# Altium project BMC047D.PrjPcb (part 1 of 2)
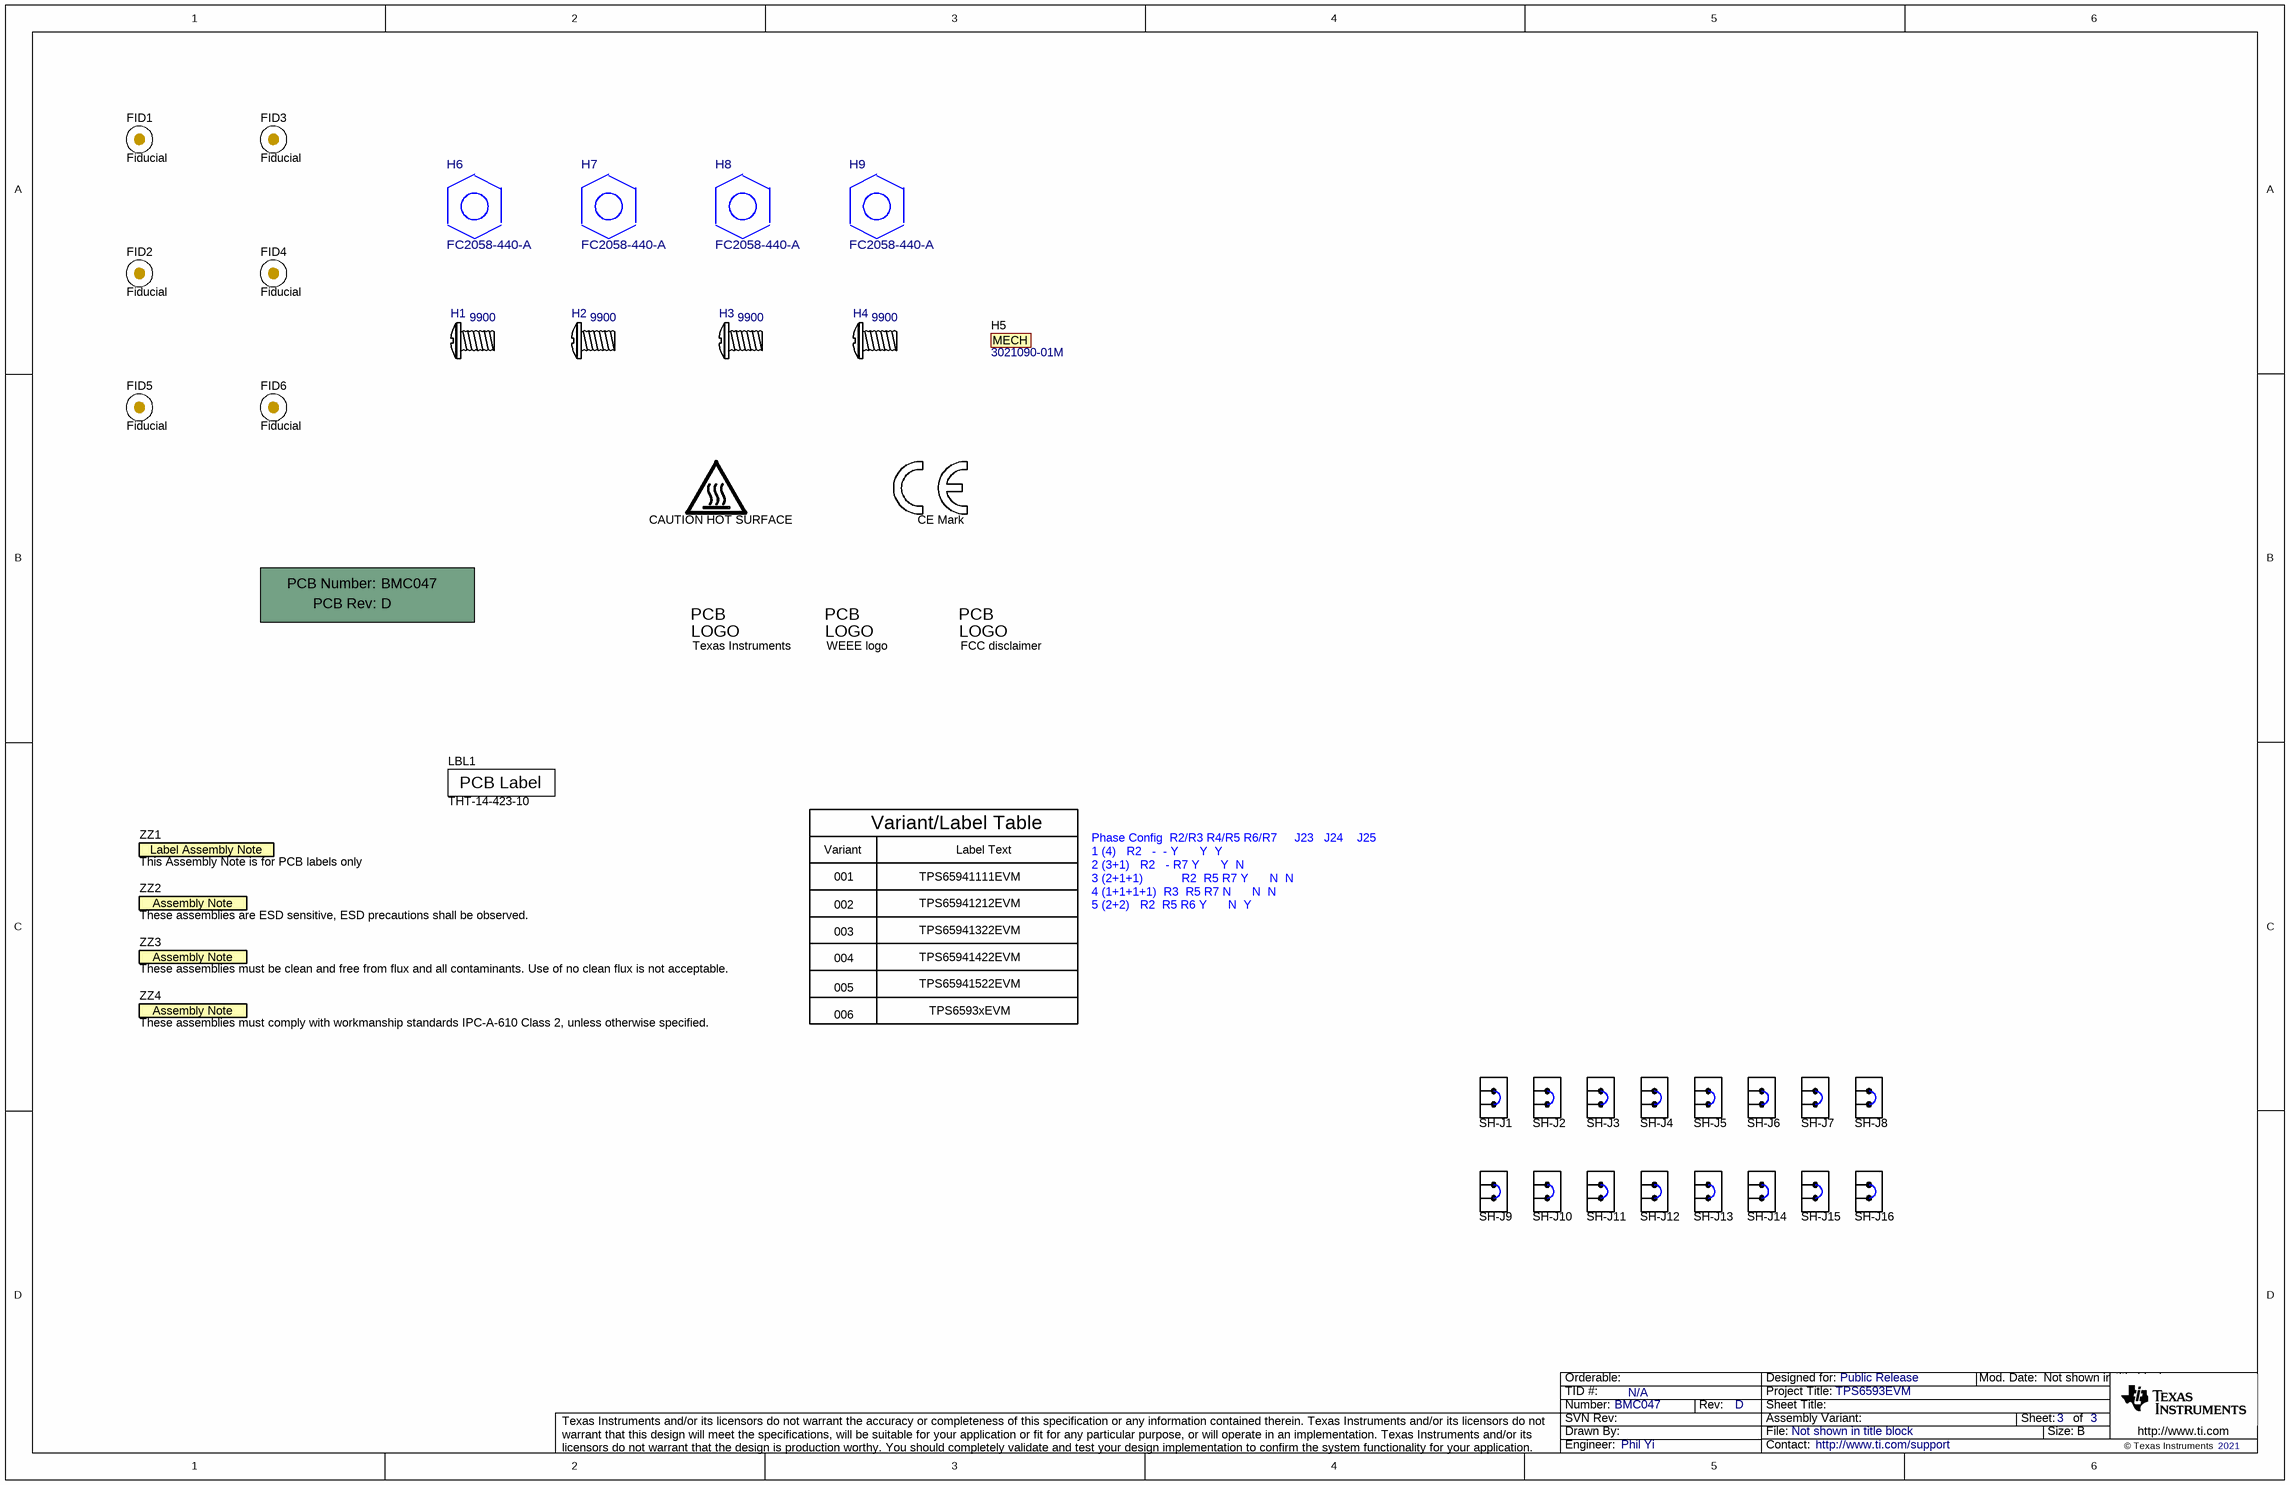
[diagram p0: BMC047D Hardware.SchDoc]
TID: N/A; TechSupport: http://www.ti.com/support; SCH_Rev: D; PRJ_Title: TPS6593EVM; PRJ_Number: BMC047; PRJ_Engineer: Phil Yi; PRJ_Customer: Public Release; PCB_Rev: D; PCB_Layout: Phil Yi; CopyrightYear: 2021
3 sheets, 331 parts. Net scope: global (net labels, ports and power ports of the same name join across sheets).
Board file: BMC047D.PcbDoc
Sheets:
  BMC047D Hardware.SchDoc
  BMC047D Main.SchDoc
  BMC047D USB.SchDoc

## Sheet BMC047D Hardware.SchDoc
size 431 x 279 mm; Date: Not shown in title block; ApprovedBy: Not shown in title block; CheckedBy: Not shown in title block; Author: Not shown in title block; CompanyName: Not shown in title block; Engineer: Not shown in title block; Organization: Not shown in title block; Address1: Not shown in title block; Address2: Not shown in title block; Address3: Not shown in title block; Address4: Not shown in title block; DocumentNumber: 3; Revision: Use project parameter SCH_Rev; SheetNumber: 3; SheetTotal: 3; PageSetup: Record=PageOptions¦CenterHorizontal=True¦CenterVertical=True¦PrintScale=1.00¦XCorrection=1.00¦YCorrection=1.00¦PrintKind=0¦BorderSize=5000000¦LeftOffset=0¦BottomOffset=0¦Orientation=2¦PaperLength=1000¦PaperWidth=1000¦Scale=100¦PaperSource=15¦PrintQuality=600¦MediaType=1¦DitherType=10¦PaperKind=Letter¦PrintScaleMode=1

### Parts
!PCB1  Printed Circuit Board  (value not drawn)  (mechanical)
FID1  Fiducial  [Fiducial10-30]  (no BOM)
FID2  Fiducial  [Fiducial10-30]  (no BOM)
FID3  Fiducial  [Fiducial10-30]  (no BOM)
FID4  Fiducial  [Fiducial10-30]  (no BOM)
FID5  Fiducial  [Fiducial10-30]  (no BOM)
FID6  Fiducial  [Fiducial10-30]  (no BOM)
H1  9900  (mechanical)
H2  9900  (mechanical)
H3  9900  (mechanical)
H4  9900  (mechanical)
H5  3021090-01M  (mechanical)
H6  FC2058-440-A  [FP-FC2058-440-A_SPACER-MFG]  (mechanical)
H7  FC2058-440-A  [FP-FC2058-440-A_SPACER-MFG]  (mechanical)
H8  FC2058-440-A  [FP-FC2058-440-A_SPACER-MFG]  (mechanical)
H9  FC2058-440-A  [FP-FC2058-440-A_SPACER-MFG]  (mechanical)
LBL1  THT-14-423-10  [Label_650x200]
LOGO1  CAUTION HOT SURFACE  [IEC_HotSurface_Small]  (no BOM)
Logo2  Texas Instruments  [TI_Stacked_Overlay_Small]  (no BOM)
Logo3  WEEE logo  [WEEE_Minimum]  (no BOM)
Logo4  CE Mark  [CE_Mark_5mm]  (no BOM)
Logo5  FCC disclaimer  [FCC_disclaimer_stacked]  (no BOM)
SH-J1  881545-2  [TE_881545-2]  (value not drawn)
SH-J2  881545-2  [TE_881545-2]  (value not drawn)
SH-J3  881545-2  [TE_881545-2]  (value not drawn)
SH-J4  881545-2  [TE_881545-2]  (value not drawn)
SH-J5  881545-2  [TE_881545-2]  (value not drawn)
SH-J6  881545-2  [TE_881545-2]  (value not drawn)
SH-J7  881545-2  [TE_881545-2]  (value not drawn)
SH-J8  881545-2  [TE_881545-2]  (value not drawn)
SH-J9  881545-2  [TE_881545-2]  (value not drawn)
SH-J10  881545-2  [TE_881545-2]  (value not drawn)
SH-J11  881545-2  [TE_881545-2]  (value not drawn)
SH-J12  881545-2  [TE_881545-2]  (value not drawn)
SH-J13  881545-2  [TE_881545-2]  (value not drawn)
SH-J14  881545-2  [TE_881545-2]  (value not drawn)
SH-J15  881545-2  [TE_881545-2]  (value not drawn)
SH-J16  881545-2  [TE_881545-2]  (value not drawn)
ZZ1  This Assembly Note is for PCB labels only  [AssemblyNoteLabel]  (no BOM)
ZZ2  These assemblies are ESD sensitive, ESD precautions shall be observed.  [AssemblyNote]  (no BOM)
ZZ3  These assemblies must be clean and free from flux and all contaminants. Use of no clean flux is not acceptable.  [AssemblyNote]  (no BOM)
ZZ4  These assemblies must comply with workmanship standards IPC-A-610 Class 2, unless otherwise specified.  [AssemblyNote]  (no BOM)

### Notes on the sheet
- Variant/Label Table
- Variant
- 001
- 002
- TPS65941111EVM
- TPS65941212EVM
- Label Text
- 003
- 004
- TPS65941322EVM
- TPS65941422EVM
- Phase Config	 R2/R3	R4/R5	R6/R7     J23   J24    J25
  1 (4)		 R2	  -	 -	Y      Y	 Y
  2 (3+1)		 R2	  -	R7	Y      Y	 N
  3 (2+1+1)	        	 R2	 R5	R7	Y      N	 N
  4 (1+1+1+1)	 R3	 R5	R7	N      N	 N
  5 (2+2)		 R2	 R5	R6	Y      N	 Y
- 005
- 006
- TPS65941522EVM
- TPS6593xEVM

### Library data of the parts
!PCB1 = CMP-0003618-2: Manufacturer: Any; PartNumber: BMC047
FID1-FID6 = CMP-0077181-1: Fiducial mark.  There is nothing to buy or mount.
H1-H4 = CMP-0003916-1: MACHINE SCREW PAN PHILLIPS 4-40; Manufacturer: Keystone; CompType: Hardware
H5 = CMP-0080604-2: USB A MALE TO USB C Male; Manufacturer: Qualtek; CompType: Mechanical
H6-H9 = CMP-0088082-1: Manufacturer: Fascomp; Symbol Name: SYM-FC2058-440-A
LBL1 = CMP-0003625-1: Manufacturer: Brady
LOGO1 = CMP-0074837-2: IEC 61010-1 Hot Surface Warning; Manufacturer: Texas Instruments; SymbolCreator: a0412235; CompType: IC; AEC Category: Q200
Logo2 = CMP-0074838-1: Texas Instrument Corporate Signature; Library Reference: Logo; SymbolCreator: a0412235; Lib Reference: TI_Logo
Logo3 = CMP-0074769-1
Logo4 = CMP-0074844-1: SymbolCreator: a0412235
Logo5 = CMP-0074847-1: FCC_disclaimer; Library Reference: Logo
SH-J1-SH-J16 = CMP-0003677-2: Shunt, 100mil, Gold plated, Black; Manufacturer: TE Connectivity
ZZ1 = CMP-0003616-3
ZZ2 = CMP-0077236-1
ZZ3 = CMP-0077237-1
ZZ4 = CMP-0077238-1

## Sheet BMC047D Main.SchDoc
size 431 x 279 mm; Date: Not shown in title block; ApprovedBy: Not shown in title block; CheckedBy: Not shown in title block; Author: Not shown in title block; CompanyName: Not shown in title block; Engineer: Not shown in title block; Organization: Not shown in title block; Address1: Not shown in title block; Address2: Not shown in title block; Address3: Not shown in title block; Address4: Not shown in title block; DocumentNumber: 1; Revision: Use project parameter SCH_Rev; SheetNumber: 1; SheetTotal: 3; PageSetup: Record=PageOptions¦CenterHorizontal=True¦CenterVertical=True¦PrintScale=1.00¦XCorrection=1.00¦YCorrection=1.00¦PrintKind=0¦BorderSize=5000000¦LeftOffset=0¦BottomOffset=0¦Orientation=2¦PaperLength=1000¦PaperWidth=1000¦Scale=100¦PaperSource=15¦PrintQuality=600¦MediaType=1¦DitherType=10¦PaperKind=Letter¦PrintScaleMode=1
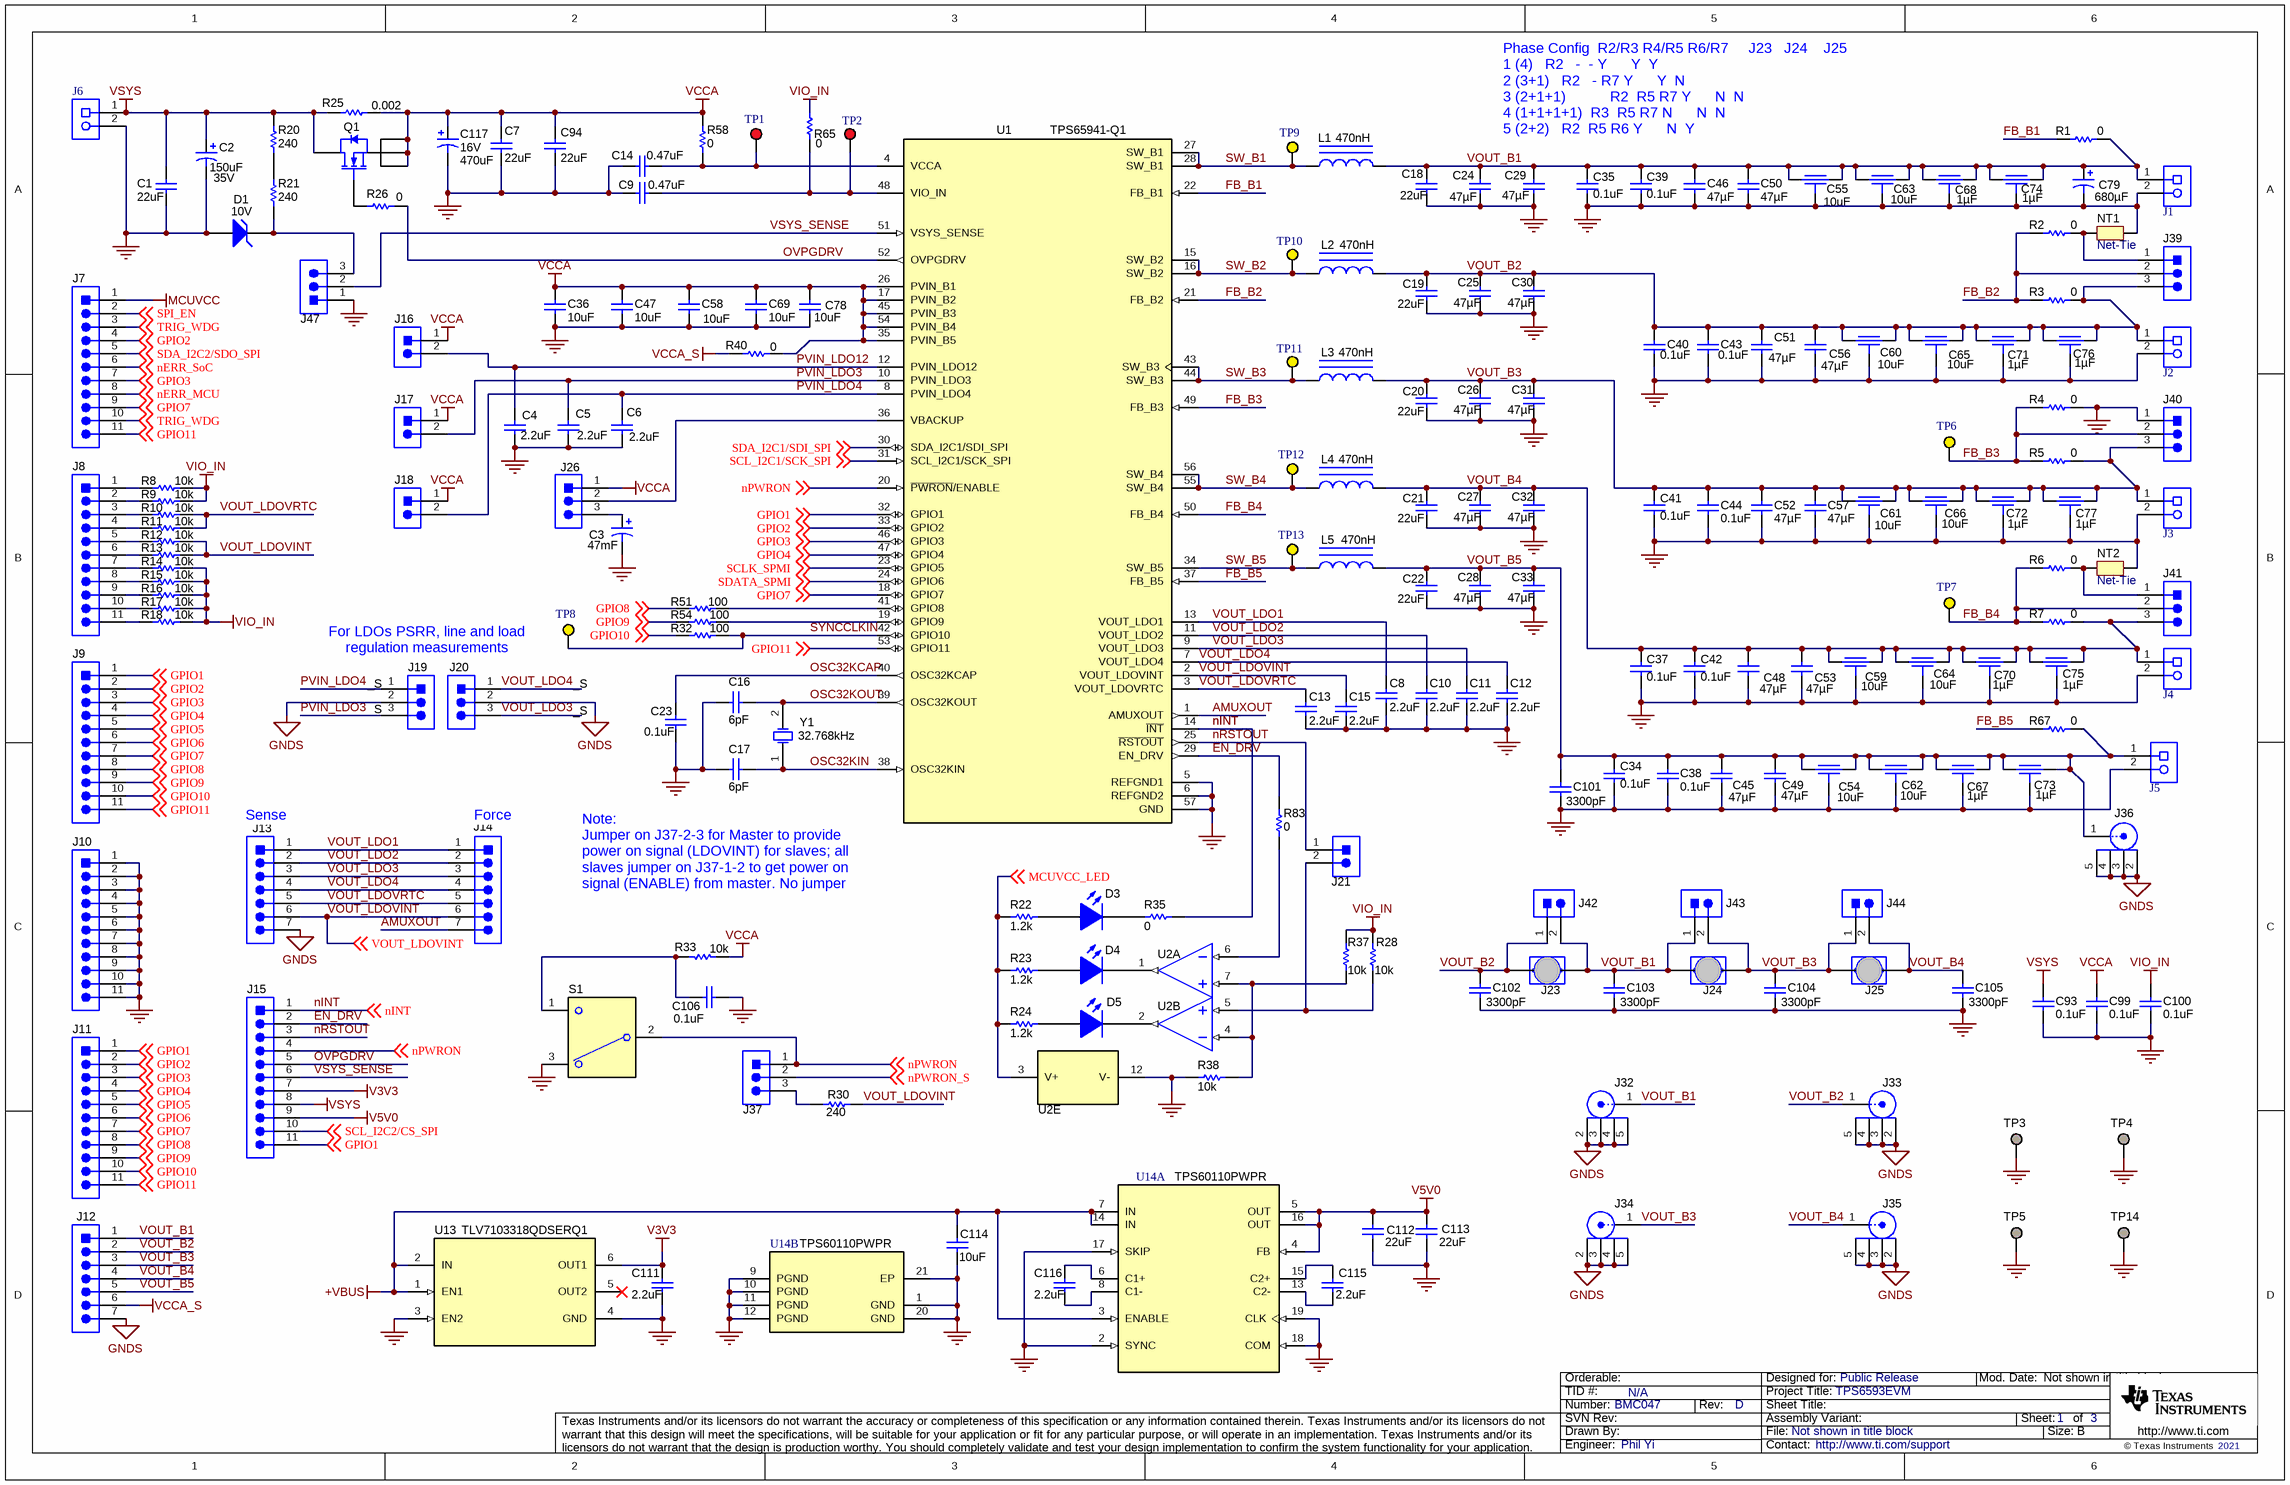
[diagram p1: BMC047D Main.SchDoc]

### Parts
C1  ValueDisplayed: 22uF  [1206_180L]  (hidden comment: CGA5L1X7R0J226M160AC)
C2  Value2: 35V  ValueDisplayed: 150uF  [SM_RADIAL_8MM]  (hidden comment: UUD1V151MNL1GS)
C3  Cap_F: 47mF  [DX-H_1150x500]  (hidden comment: DX-5R5H473U)
C4  ValueDisplayed: 2.2uF  [0603L]  (hidden comment: CGA3E1X7S1C225M080AC)
C5  ValueDisplayed: 2.2uF  [0603L]  (hidden comment: CGA3E1X7S1C225M080AC)
C6  ValueDisplayed: 2.2uF  [0603L]  (hidden comment: CGA3E1X7S1C225M080AC)
C7  ValueDisplayed: 22uF  [1206_180L]  (hidden comment: CGA5L1X7R0J226M160AC)
C8  ValueDisplayed: 2.2uF  [0603L]  (hidden comment: CGA3E1X7S1C225M080AC)
C9  ValueDisplayed: 0.47uF  [0402L]  (hidden comment: GCM155C71A474KE36D)
C10  ValueDisplayed: 2.2uF  [0603L]  (hidden comment: CGA3E1X7S1C225M080AC)
C11  ValueDisplayed: 2.2uF  [0603L]  (hidden comment: CGA3E1X7S1C225M080AC)
C12  ValueDisplayed: 2.2uF  [0603L]  (hidden comment: CGA3E1X7S1C225M080AC)
C13  ValueDisplayed: 2.2uF  [0603L]  (hidden comment: CGA3E1X7S1C225M080AC)
C14  ValueDisplayed: 0.47uF  [0402L]  (hidden comment: GCM155C71A474KE36D)
C15  ValueDisplayed: 2.2uF  [0603L]  (hidden comment: CGA3E1X7S1C225M080AC)
C16  Cap_F: 6pF  [FP-GCM1555C1H6R0CA16_0402-MFG]  (hidden comment: GCM1555C1H6R0CA16)
C17  Cap_F: 6pF  [FP-GCM1555C1H6R0CA16_0402-MFG]  (hidden comment: GCM1555C1H6R0CA16)
C18  ValueDisplayed: 22uF  [1206_180L]  (hidden comment: CGA5L1X7R0J226M160AC)
C19  ValueDisplayed: 22uF  [1206_180L]  (hidden comment: CGA5L1X7R0J226M160AC)
C20  ValueDisplayed: 22uF  [1206_180L]  (hidden comment: CGA5L1X7R0J226M160AC)
C21  ValueDisplayed: 22uF  [1206_180L]  (hidden comment: CGA5L1X7R0J226M160AC)
C22  ValueDisplayed: 22uF  [1206_180L]  (hidden comment: CGA5L1X7R0J226M160AC)
C23  ValueDisplayed: 0.1uF  [0402L]  (hidden comment: GCM155R71C104KA55D)
C24  Cap_F: 47µF  [1210_280]  (hidden comment: 47uF)
C25  Cap_F: 47µF  [1210_280]  (hidden comment: 47uF)
C26  Cap_F: 47µF  [1210_280]  (hidden comment: 47uF)
C27  Cap_F: 47µF  [1210_280]  (hidden comment: 47uF)
C28  Cap_F: 47µF  [1210_280]  (hidden comment: 47uF)
C29  Cap_F: 47µF  [1210_280]  (hidden comment: 47uF)
C30  Cap_F: 47µF  [1210_280]  (hidden comment: 47uF)
C31  Cap_F: 47µF  [1210_280]  (hidden comment: 47uF)
C32  Cap_F: 47µF  [1210_280]  (hidden comment: 47uF)
C33  Cap_F: 47µF  [1210_280]  (hidden comment: 47uF)
C34  ValueDisplayed: 0.1uF  [0402L]  (hidden comment: GCM155R71C104KA55D)
C35  ValueDisplayed: 0.1uF  [0402L]  (hidden comment: GCM155R71C104KA55D)
C36  ValueDisplayed: 10uF  [0805L]  (hidden comment: CGA4J1X7S1C106K125AC)
C37  ValueDisplayed: 0.1uF  [0402L]  (hidden comment: GCM155R71C104KA55D)
C38  ValueDisplayed: 0.1uF  [0402L]  (hidden comment: GCM155R71C104KA55D)
C39  ValueDisplayed: 0.1uF  [0402L]  (hidden comment: GCM155R71C104KA55D)
C40  ValueDisplayed: 0.1uF  [0402L]  (hidden comment: GCM155R71C104KA55D)
C41  ValueDisplayed: 0.1uF  [0402L]  (hidden comment: GCM155R71C104KA55D)
C42  ValueDisplayed: 0.1uF  [0402L]  (hidden comment: GCM155R71C104KA55D)
C43  ValueDisplayed: 0.1uF  [0402L]  (hidden comment: GCM155R71C104KA55D)
C44  ValueDisplayed: 0.1uF  [0402L]  (hidden comment: GCM155R71C104KA55D)
C45  Cap_F: 47µF  [1206_190]  (hidden comment: GCM31CD70G476ME)
C46  Cap_F: 47µF  [1206_190L]  (hidden comment: GCM31CD70G476ME)
C47  ValueDisplayed: 10uF  [0805L]  (hidden comment: CGA4J1X7S1C106K125AC)
C48  Cap_F: 47µF  [1206_190L]  (hidden comment: GCM31CD70G476ME)
C49  Cap_F: 47µF  [1206_190]  (hidden comment: GCM31CD70G476ME)
C50  Cap_F: 47µF  [1206_190L]  (hidden comment: GCM31CD70G476ME)
C51  Cap_F: 47µF  [1206_190L]  (hidden comment: GCM31CD70G476ME)
C52  Cap_F: 47µF  [1206_190L]  (hidden comment: GCM31CD70G476ME)
C53  Cap_F: 47µF  [1206_190L]  (hidden comment: GCM31CD70G476ME)
C54  10uF  [NFM18HC]
C55  10uF  [NFM18HC]
C56  Cap_F: 47µF  [1206_190L]  (hidden comment: GCM31CD70G476ME)
C57  Cap_F: 47µF  [1206_190L]  (hidden comment: GCM31CD70G476ME)
C58  ValueDisplayed: 10uF  [0805L]  (hidden comment: CGA4J1X7S1C106K125AC)
C59  10uF  [NFM18HC]
C60  10uF  [NFM18HC]
C61  10uF  [NFM18HC]
C62  10uF  [NFM18HC]
C63  10uF  [NFM18HC]
C64  10uF  [NFM18HC]
C65  10uF  [NFM18HC]
C66  10uF  [NFM18HC]
C67  ValueDisplayed: 1µF  [FP-NFM15HC105D0G3_0402-MFG]  (hidden comment: NFM15HC105D0G3)
C68  ValueDisplayed: 1µF  [FP-NFM15HC105D0G3_0402-MFG]  (hidden comment: NFM15HC105D0G3)
C69  ValueDisplayed: 10uF  [0805L]  (hidden comment: CGA4J1X7S1C106K125AC)
C70  ValueDisplayed: 1µF  [FP-NFM15HC105D0G3_0402-MFG]  (hidden comment: NFM15HC105D0G3)
C71  ValueDisplayed: 1µF  [FP-NFM15HC105D0G3_0402-MFG]  (hidden comment: NFM15HC105D0G3)
C72  ValueDisplayed: 1µF  [FP-NFM15HC105D0G3_0402-MFG]  (hidden comment: NFM15HC105D0G3)
C73  ValueDisplayed: 1µF  [FP-NFM15HC105D0G3_0402-MFG]  (hidden comment: NFM15HC105D0G3)
C74  ValueDisplayed: 1µF  [FP-NFM15HC105D0G3_0402-MFG]  (hidden comment: NFM15HC105D0G3)
C75  ValueDisplayed: 1µF  [FP-NFM15HC105D0G3_0402-MFG]  (hidden comment: NFM15HC105D0G3)
C76  ValueDisplayed: 1µF  [FP-NFM15HC105D0G3_0402-MFG]  (hidden comment: NFM15HC105D0G3)
C77  ValueDisplayed: 1µF  [FP-NFM15HC105D0G3_0402-MFG]  (hidden comment: NFM15HC105D0G3)
C78  ValueDisplayed: 10uF  [0805L]  (hidden comment: CGA4J1X7S1C106K125AC)
C79  ValueDisplayed: 680µF  [7343-40]  (hidden comment: T510X687K006AGA023)
C93  ValueDisplayed: 0.1uF  [0402L]  (hidden comment: GCM155R71C104KA55D)
C94  ValueDisplayed: 22uF  [1206_180L]  (hidden comment: CGA5L1X7R0J226M160AC)
C99  ValueDisplayed: 0.1uF  [0402L]  (hidden comment: GCM155R71C104KA55D)
C100  ValueDisplayed: 0.1uF  [0402L]  (hidden comment: GCM155R71C104KA55D)
C101  ValueDisplayed: 3300pF  [0603L]  (hidden comment: C0603C332K5RACTU)
C102  ValueDisplayed: 3300pF  [0603L]  (hidden comment: C0603C332K5RACTU)
C103  ValueDisplayed: 3300pF  [0603L]  (hidden comment: C0603C332K5RACTU)
C104  ValueDisplayed: 3300pF  [0603L]  (hidden comment: C0603C332K5RACTU)
C105  ValueDisplayed: 3300pF  [0603L]  (hidden comment: C0603C332K5RACTU)
C106  ValueDisplayed: 0.1uF  [0402L]  (hidden comment: GCM155R71C104KA55D)
C111  ValueDisplayed: 2.2uF  [0603L]  (hidden comment: CGA3E1X7S1C225M080AC)
C112  ValueDisplayed: 22uF  [0603S]  (hidden comment: GRM188R60J226MEA0D)
C113  ValueDisplayed: 22uF  [0603S]  (hidden comment: GRM188R60J226MEA0D)
C114  ValueDisplayed: 10uF  [0805L]  (hidden comment: CGA4J1X7S1C106K125AC)
C115  ValueDisplayed: 2.2uF  [0603L]  (hidden comment: CGA3E1X7S1C225M080AC)
C116  ValueDisplayed: 2.2uF  [0603L]  (hidden comment: CGA3E1X7S1C225M080AC)
C117  VDC_V: 16V  ValueDisplayed: 470uF  [SM_RADIAL_8MM]  (hidden comment: UUD1C471MNL1GS)
D1  value 10V  [SOD-323]  (hidden comment: MM3Z10VST1G)
D3  LB Q39G-L2N2-35-1  [LB Q39G_BLUE]  (value not drawn)
D4  LB Q39G-L2N2-35-1  [LB Q39G_BLUE]  (value not drawn)
D5  LB Q39G-L2N2-35-1  [LB Q39G_BLUE]  (value not drawn)
J1  1792863  [Phoenix_1792863]  (value not drawn)
J2  1792863  [Phoenix_1792863]  (value not drawn)
J3  1792863  [Phoenix_1792863]  (value not drawn)
J4  1792863  [Phoenix_1792863]  (value not drawn)
J5  1792863  [Phoenix_1792863]  (value not drawn)
J6  1792863  [Phoenix_1792863]  (value not drawn)
J7  TSW-111-07-G-S  [TSW-111-07-G-S]  (value not drawn)
J8  TSW-111-07-G-S  [TSW-111-07-G-S]  (value not drawn)
J9  TSW-111-07-G-S  [TSW-111-07-G-S]  (value not drawn)
J10  TSW-111-07-G-S  [TSW-111-07-G-S]  (value not drawn)
J11  TSW-111-07-G-S  [TSW-111-07-G-S]  (value not drawn)
J12  TSW-107-07-G-S  [TSW-107-XX-XXX-S]  (value not drawn)
J13  TSW-107-07-G-S  [TSW-107-XX-XXX-S]  (value not drawn)
J14  TSW-107-07-G-S  [TSW-107-XX-XXX-S]  (value not drawn)
J15  TSW-111-07-G-S  [TSW-111-07-G-S]  (value not drawn)
J16  TSW-102-23-T-S  [Samtec_TSW-102-23-X-S]  (value not drawn)
J17  TSW-102-23-T-S  [Samtec_TSW-102-23-X-S]  (value not drawn)
J18  TSW-102-23-T-S  [Samtec_TSW-102-23-X-S]  (value not drawn)
J19  61300311121  [WURTH_61300311121]  (value not drawn)
J20  61300311121  [WURTH_61300311121]  (value not drawn)
J21  TSW-102-23-T-S  [Samtec_TSW-102-23-X-S]  (value not drawn)
J23  S1911-46R  [HARWIN_S1911-46R]  (value not drawn)
J24  S1911-46R  [HARWIN_S1911-46R]  (value not drawn)
J25  S1911-46R  [HARWIN_S1911-46R]  (value not drawn)
J26  61300311121  [WURTH_61300311121]  (value not drawn)
J32  SMA-J-P-H-ST-TH1  [SAMTEC_SMA-J-P-H-ST-TH1]  (value not drawn)
J33  SMA-J-P-H-ST-TH1  [SAMTEC_SMA-J-P-H-ST-TH1]  (value not drawn)
J34  SMA-J-P-H-ST-TH1  [SAMTEC_SMA-J-P-H-ST-TH1]  (value not drawn)
J35  SMA-J-P-H-ST-TH1  [SAMTEC_SMA-J-P-H-ST-TH1]  (value not drawn)
J36  SMA-J-P-H-ST-TH1  [SAMTEC_SMA-J-P-H-ST-TH1]  (value not drawn)
J37  61300311121  [WURTH_61300311121]  (value not drawn)
J39  TSM-103-01-L-SV  [Samtec_TSM-103-01-X-SV]  (value not drawn)
J40  TSM-103-01-L-SV  [Samtec_TSM-103-01-X-SV]  (value not drawn)
J41  TSM-103-01-L-SV  [Samtec_TSM-103-01-X-SV]  (value not drawn)
J42  TSM-102-01-T-SV-P-TR  [Samtec_TSM-102-01-T-SV-P-TR]  (value not drawn)
J43  TSM-102-01-T-SV-P-TR  [Samtec_TSM-102-01-T-SV-P-TR]  (value not drawn)
J44  TSM-102-01-T-SV-P-TR  [Samtec_TSM-102-01-T-SV-P-TR]  (value not drawn)
J47  61300311121  [WURTH_61300311121]  (value not drawn)
L1  470nH  [TFM322512]
L2  470nH  [TFM322512]
L3  470nH  [TFM322512]
L4  470nH  [TFM322512]
L5  470nH  [TFM322512]
NT1  Net-Tie  [Net-Tie_0805_HV_NoOverlay]  (net tie, no BOM)
NT2  Net-Tie  [Net-Tie_0805_HV_NoOverlay]  (net tie, no BOM)
Q1  NVMFS4C05NT1G  [SO-8FL]  (value not drawn)
R1  ValueDisplayed: 0  [0402L]  (hidden comment: RK73Z1ETTP)
R2  ValueDisplayed: 0  [0402L]  (hidden comment: RK73Z1ETTP)
R3  ValueDisplayed: 0  [0402L]  (hidden comment: RK73Z1ETTP)
R4  ValueDisplayed: 0  [0402L]  (hidden comment: RK73Z1ETTP)
R5  ValueDisplayed: 0  [0402L]  (hidden comment: RK73Z1ETTP)
R6  ValueDisplayed: 0  [0402L]  (hidden comment: RK73Z1ETTP)
R7  ValueDisplayed: 0  [0402L]  (hidden comment: RK73Z1ETTP)
R8  ValueDisplayed: 10k  [0402L]  (hidden comment: CRCW040210K0JNED)
R9  ValueDisplayed: 10k  [0402L]  (hidden comment: CRCW040210K0JNED)
R10  ValueDisplayed: 10k  [0402L]  (hidden comment: CRCW040210K0JNED)
R11  ValueDisplayed: 10k  [0402L]  (hidden comment: CRCW040210K0JNED)
R12  ValueDisplayed: 10k  [0402L]  (hidden comment: CRCW040210K0JNED)
R13  ValueDisplayed: 10k  [0402L]  (hidden comment: CRCW040210K0JNED)
R14  ValueDisplayed: 10k  [0402L]  (hidden comment: CRCW040210K0JNED)
R15  ValueDisplayed: 10k  [0402L]  (hidden comment: CRCW040210K0JNED)
R16  ValueDisplayed: 10k  [0402L]  (hidden comment: CRCW040210K0JNED)
R17  ValueDisplayed: 10k  [0402L]  (hidden comment: CRCW040210K0JNED)
R18  ValueDisplayed: 10k  [0402L]  (hidden comment: CRCW040210K0JNED)
R20  ValueDisplayed: 240  [0402L]  (hidden comment: CRCW0402240RJNED)
R21  ValueDisplayed: 240  [0402L]  (hidden comment: CRCW0402240RJNED)
R22  ValueDisplayed: 1.2k  [0402L]  (hidden comment: CRCW04021K20JNED)
R23  ValueDisplayed: 1.2k  [0402L]  (hidden comment: CRCW04021K20JNED)
R24  ValueDisplayed: 1.2k  [0402L]  (hidden comment: CRCW04021K20JNED)
R25  ValueDisplayed: 0.002  [0508S]  (hidden comment: Resistor)
R26  ValueDisplayed: 0  [0402L]  (hidden comment: RK73Z1ETTP)
R28  ValueDisplayed: 10k  [0402L]  (hidden comment: CRCW040210K0JNED)
R30  ValueDisplayed: 240  [0402L]  (hidden comment: CRCW0402240RJNED)
R32  ValueDisplayed: 100  [0402L]  (hidden comment: CRCW0402100RJNED)
R33  ValueDisplayed: 10k  [0402L]  (hidden comment: CRCW040210K0JNED)
R35  ValueDisplayed: 0  [0402L]  (hidden comment: RK73Z1ETTP)
R37  ValueDisplayed: 10k  [0402L]  (hidden comment: CRCW040210K0JNED)
R38  ValueDisplayed: 10k  [0402L]  (hidden comment: CRCW040210K0JNED)
R40  ValueDisplayed: 0  [0402L]  (hidden comment: RK73Z1ETTP)
R51  ValueDisplayed: 100  [0402L]  (hidden comment: CRCW0402100RJNED)
R54  ValueDisplayed: 100  [0402L]  (hidden comment: CRCW0402100RJNED)
R58  ValueDisplayed: 0  [0402L]  (hidden comment: RK73Z1ETTP)
R65  ValueDisplayed: 0  [0402L]  (hidden comment: RK73Z1ETTP)
R67  ValueDisplayed: 0  [0402L]  (hidden comment: RK73Z1ETTP)
R83  ValueDisplayed: 0  [0402L]  (hidden comment: RK73Z1ETTP)
S1  CL-SB-12A-01T  [SW_CL-SB-12A-01]  (value not drawn)
TP1  5000  [Keystone5000]  (value not drawn)
TP2  5000  [Keystone5000]  (value not drawn)
TP3  S1751-46  [Harwin_S1751-46]  (value not drawn)
TP4  S1751-46  [Harwin_S1751-46]  (value not drawn)
TP5  S1751-46  [Harwin_S1751-46]  (value not drawn)
TP6  5004  [Keystone5004]  (value not drawn)
TP7  5004  [Keystone5004]  (value not drawn)
TP8  5004  [Keystone5004]  (value not drawn)
TP9  5004  [Keystone5004]  (value not drawn)
TP10  5004  [Keystone5004]  (value not drawn)
TP11  5004  [Keystone5004]  (value not drawn)
TP12  5004  [Keystone5004]  (value not drawn)
TP13  5004  [Keystone5004]  (value not drawn)
TP14  S1751-46  [Harwin_S1751-46]  (value not drawn)
U1  TPS65941-Q1  [RVJ0056A]
U2  LM2901AVQPWRQ1  [PW0014A_N]  (value not drawn)  (parts A,B,E of 5)
U13  TLV7103318QDSERQ1  [DSE0006A]
U14  TPS60110PWPR  [PWP0020C_N]  (parts A,B of 2)
Y1  Frequency_Fixed: 32.768kHz  [NDK_NX3215SD]  (hidden comment: NX3215SD-STD-MUS-6)

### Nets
+VBUS: C114.1 U13.1(EN1) U13.2(IN) U14.3(ENABLE) U14.7(IN) U14.14(IN)
GND: C1.2 C2.2(-) C3.2(-) C4.2 C5.2 C6.2 C7.2 C8.2 C9.1 C10.2 C11.2 C12.2 C13.2 C14.1 C15.2 C16.1 C17.1 C18.2 C19.2 C20.2 C21.2 C22.2 C23.2 C24.1 C25.1 C26.1 C27.1 C28.1 C29.1 C30.1 C31.1 C32.1 C33.1 C34.1 C35.1 C36.1 C37.1 C38.2 C39.1 C40.1 C41.1 C42.1 C43.2 C44.2 C45.2 C46.2 C47.2 C48.2 C49.2 C50.2 C51.2 C52.2 C53.2 C54.2 C55.2 C56.2 C57.2 C58.2 C59.2 C60.2 C61.2 C62.2 C63.2 C64.2 C65.2 C66.2 C67.2 C68.2 C69.2 C70.2 C71.2 C72.2 C73.2 C74.2 C75.2 C76.2 C77.2 C78.2 C79.2(-) C93.2 C94.2 C99.2 C100.2 C101.2 C102.2 C103.2 C104.2 C105.2 C106.1 C111.1 C112.2 C113.2 C114.2 C117.2(-) D1.2(A) J1.2 J2.2 J3.2 J4.2 J5.2 J6.2 J10.1 J10.2 J10.3 J10.4 J10.5 J10.6 J10.7 J10.8 J10.9 J10.10 J10.11 J40.1 J47.1 NT1.2 NT2.2 R4.2 R38.1 S1.3 TP3.1 TP4.1 TP5.1 TP14.1 U1.5(REFGND1) U1.6(REFGND2) U1.57(GND) U2.12(V-) U13.3(EN2) U13.4(GND) U14.1(GND) U14.2(SYNC) U14.9(PGND) U14.10(PGND) U14.11(PGND) U14.12(PGND) U14.17(SKIP) U14.18(COM) U14.19(CLK) U14.20(GND) U14.21(EP)
GNDS: J12.7 J13.7 J19.2 J20.2 J32.2 J32.3 J32.4 J32.5 J33.2 J33.3 J33.4 J33.5 J34.2 J34.3 J34.4 J34.5 J35.2 J35.3 J35.4 J35.5 J36.2 J36.3 J36.4 J36.5
MCUVCC: J7.1
V3V3: C111.2 J15.7 U13.6(OUT1)
V5V0: C112.1 C113.1 J15.9 U14.4(FB) U14.5(OUT) U14.16(OUT)
VCCA: C7.1 C36.2 C47.1 C58.1 C69.1 C78.1 C94.1 C99.1 C117.1(+) J16.1 J17.1 J18.1 J26.1 Q1.1(S) Q1.2(S) Q1.3(S) R25.2 R33.1 R40.2 R58.1 U1.17(PVIN_B2) U1.26(PVIN_B1) U1.35(PVIN_B5) U1.45(PVIN_B3) U1.54(PVIN_B4)
VCCA_S: J12.6 R40.1
VIO_IN: C100.1 R8.2 R9.2 R14.2 R15.2 R16.2 R17.2 R18.2 R28.2 R37.2 R65.1
VSYS: C1.1 C2.1(+) C93.1 J6.1 J15.8 Q1.5(D) R20.1 R25.1
AMUXOUT: J14.7 U1.1(AMUXOUT)
EN_DRV: J15.2 R83.1 U1.29(EN_DRV)
FB_B1: R1.1 U1.22(FB_B1)
FB_B2: J39.2 R2.1 R3.1 U1.21(FB_B2)
FB_B3: J40.2 R4.1 R5.1 TP6.1 U1.49(FB_B3)
FB_B4: J41.2 R6.1 R7.1 TP7.1 U1.50(FB_B4)
FB_B5: R67.1 U1.37(FB_B5)
GPIO1: J9.1 J11.1 J15.11 U1.32(GPIO1) ; off-sheet GPIO1
GPIO2: J7.4 J9.2 J11.2 U1.33(GPIO2) ; off-sheet GPIO2
GPIO3: J7.7 J9.3 J11.3 U1.46(GPIO3) ; off-sheet GPIO3
GPIO4: J9.4 J11.4 U1.47(GPIO4) ; off-sheet GPIO4
GPIO5: J9.5 J11.5 ; off-sheet GPIO5
GPIO6: J9.6 J11.6 ; off-sheet GPIO6
GPIO7: J7.9 J9.7 J11.7 U1.18(GPIO7) ; off-sheet GPIO7
GPIO8: J9.8 J11.8 R51.1 ; off-sheet GPIO8
GPIO9: J9.9 J11.9 R54.1 ; off-sheet GPIO9
GPIO10: J9.10 J11.10 R32.1 ; off-sheet GPIO10
GPIO11: J7.11 J9.11 J11.11 U1.53(GPIO11) ; off-sheet GPIO11
MCUVCC_LED: R22.2 R23.2 R24.2 U2.3(V+) ; off-sheet MCUVCC_LED
nERR_MCU: J7.8 ; off-sheet nERR_MCU
nERR_SoC: J7.6 ; off-sheet nERR_SoC
nINT: J15.1 R35.1 U1.14(~{INT}) ; off-sheet nINT
nPWRON: J15.4 J37.1 S1.2(COM) U1.20(~{PWRON}/ENABLE) ; off-sheet nPWRON
nPWRON_S: J37.2 ; off-sheet nPWRON_S
nRSTOUT: J15.3 J21.1 U1.25(~{RSTOUT})
OSC32KCAP: C23.1 U1.40(OSC32KCAP)
OSC32KIN: C17.2 U1.38(OSC32KIN) Y1.1(OSC1)
OSC32KOUT: C16.2 U1.39(OSC32KOUT) Y1.2(OSC2)
OVPGDRV: J15.5 R26.1 U1.52(OVPGDRV)
PVIN_LDO3: C5.1 J17.2 J19.3 U1.10(PVIN_LDO3)
PVIN_LDO4: C6.1 J18.2 J19.1 U1.8(PVIN_LDO4)
PVIN_LDO12: C4.1 J16.2 U1.12(PVIN_LDO12)
SCL_I2C1/SCK_SPI: U1.31(SCL_I2C1/SCK_SPI) ; off-sheet SCL_I2C1/SCK_SPI
SCL_I2C2/CS_SPI: J15.10 ; off-sheet SCL_I2C2/CS_SPI
SCLK_SPMI: U1.23(GPIO5) ; off-sheet SCLK_SPMI
SDA_I2C1/SDI_SPI: U1.30(SDA_I2C1/SDI_SPI) ; off-sheet SDA_I2C1/SDI_SPI
SDA_I2C2/SDO_SPI: J7.5 ; off-sheet SDA_I2C2/SDO_SPI
SDATA_SPMI: U1.24(GPIO6) ; off-sheet SDATA_SPMI
SPI_EN: J7.2 ; off-sheet SPI_EN
SW_B1: L1.1 TP9.1 U1.27(SW_B1) U1.28(SW_B1)
SW_B2: L2.1 TP10.1 U1.15(SW_B2) U1.16(SW_B2)
SW_B3: L3.1 TP11.1 U1.43(SW_B3) U1.44(SW_B3)
SW_B4: L4.1 TP12.1 U1.55(SW_B4) U1.56(SW_B4)
SW_B5: L5.1 TP13.1 U1.34(SW_B5)
SYNCCLKIN: R32.2 TP8.1 U1.42(GPIO10)
TRIG_WDG: J7.3 J7.10 ; off-sheet TRIG_WDG
VOUT_B1: C18.1 C24.2 C29.2 C35.2 C39.2 C46.1 C50.1 C55.1 C55.3 C63.1 C63.3 C68.1 C68.3 C74.1 C74.3 C79.1(+) C103.1 J1.1 J12.1 J23.1 J24.2 J32.1 J42.2 J43.1 L1.2 R1.2
VOUT_B2: C19.1 C25.2 C30.2 C40.2 C43.1 C51.1 C56.1 C60.1 C60.3 C65.1 C65.3 C71.1 C71.3 C76.1 C76.3 C102.1 J2.1 J12.2 J23.2 J33.1 J39.3 J42.1 L2.2 R3.2
VOUT_B3: C20.1 C26.2 C31.2 C41.2 C44.1 C52.1 C57.1 C61.1 C61.3 C66.1 C66.3 C72.1 C72.3 C77.1 C77.3 C104.1 J3.1 J12.3 J24.1 J25.2 J34.1 J40.3 J43.2 J44.1 L3.2 R5.2
VOUT_B4: C21.1 C27.2 C32.2 C37.2 C42.2 C48.1 C53.1 C59.1 C59.3 C64.1 C64.3 C70.1 C70.3 C75.1 C75.3 C105.1 J4.1 J12.4 J25.1 J35.1 J41.3 J44.2 L4.2 R7.2
VOUT_B5: C22.1 C28.2 C33.2 C34.2 C38.1 C45.1 C49.1 C54.1 C54.3 C62.1 C62.3 C67.1 C67.3 C73.1 C73.3 C101.1 J5.1 J12.5 J36.1 L5.2 R67.2
VOUT_LDO1: C8.1 J13.1 J14.1 U1.13(VOUT_LDO1)
VOUT_LDO2: C10.1 J13.2 J14.2 U1.11(VOUT_LDO2)
VOUT_LDO3: C11.1 J13.3 J14.3 J20.3 U1.9(VOUT_LDO3)
VOUT_LDO4: C12.1 J13.4 J14.4 J20.1 U1.7(VOUT_LDO4)
VOUT_LDOVINT: C15.1 J13.6 J14.6 R12.2 R13.2 R30.1 U1.2(VOUT_LDOVINT) ; off-sheet VOUT_LDOVINT
VOUT_LDOVRTC: C13.1 J13.5 J14.5 R10.2 R11.2 U1.3(VOUT_LDOVRTC)
VSYS_SENSE: J15.6 J47.2 U1.51(VSYS_SENSE)
NetC3_1: C3.1(+) J26.3
NetC9_2: C9.2 R65.2 TP2.1 U1.48(VIO_IN)
NetC14_2: C14.2 R58.2 TP1.1 U1.4(VCCA)
NetC106_2: C106.2 R33.2 S1.1
NetC115_1: C115.1 U14.13(C2-)
NetC115_2: C115.2 U14.15(C2+)
NetC116_1: C116.1 U14.8(C1-)
NetC116_2: C116.2 U14.6(C1+)
NetD1_1: D1.1(K) J47.3 R21.2
NetD3_1: D3.1(A) R22.1
NetD3_2: D3.2(K) R35.2
NetD4_1: D4.1(A) R23.1
NetD4_2: D4.2(K) U2.1(OUT2)
NetD5_1: D5.1(A) R24.1
NetD5_2: D5.2(K) U2.2(OUT1)
NetJ8_1: J8.1 R8.1
NetJ8_2: J8.2 R9.1
NetJ8_3: J8.3 R10.1
NetJ8_4: J8.4 R11.1
NetJ8_5: J8.5 R12.1
NetJ8_6: J8.6 R13.1
NetJ8_7: J8.7 R14.1
NetJ8_8: J8.8 R15.1
NetJ8_9: J8.9 R16.1
NetJ8_10: J8.10 R17.1
NetJ8_11: J8.11 R18.1
NetJ21_2: J21.2 R28.1 U2.5(+IN1)
NetJ26_2: J26.2 U1.36(VBACKUP)
NetJ37_3: J37.3 R30.2
NetJ39_1: J39.1 NT1.1 R2.2
NetJ41_1: J41.1 NT2.1 R6.2
NetQ1_4: Q1.4(G) R26.2
NetR20_2: R20.2 R21.1
NetR37_1: R37.1 R38.2 U2.4(-IN1) U2.7(+IN2)
NetR51_2: R51.2 U1.41(GPIO8)
NetR54_2: R54.2 U1.19(GPIO9)
NetR83_2: R83.2 U2.6(-IN2)

Not connected (* = marked no-connect by the designer): U13 5(OUT2)*

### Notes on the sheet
- Phase Config	 R2/R3	R4/R5	R6/R7     J23   J24    J25
  1 (4)		 R2	  -	 -	Y      Y	 Y
  2 (3+1)		 R2	  -	R7	Y      Y	 N
  3 (2+1+1)	        	 R2	 R5	R7	Y      N	 N
  4 (1+1+1+1)	 R3	 R5	R7	N      N	 N
  5 (2+2)		 R2	 R5	R6	Y      N	 Y
- For LDOs PSRR, line and load regulation measurements
- (near J19) _S
- (near TP8) _S
- _S
- (near J13) Sense
- (near J14) Force
- Note:
  Jumper on J37-2-3 for Master to provide power on signal (LDOVINT) for slaves; all slaves jumper on J37-1-2 to get power on signal (ENABLE) from master. No jumper on J37 when single PMIC is used.

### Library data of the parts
C1 C7 C18-C22 C94 = CMP-0008770-2: CAP, CERM, 22 uF, 6.3 V, +/- 10%, X7R, AEC-Q200 Grade 1, 1206; Manufacturer: TDK; TaMin_C: -55°C; ESR_ohm: 1.872m; Polarized: N; SizeAreaWB_mm2: 10.92; Value1: 0.001872 ohm; U/M: EA; Value: 22uF; SizeZ_mm: 1.8; SizeX_mm: 3.2; SizeY_mm: 1.6; Cap_Case: 1206_180; Value2: 6.3V; SizeArea_mm2: 5.12; AEC Qualified: Y; Cap_F: 22µF; IRMS_A: 5.30203A; AEC Grade: 1; AEC Category: Q200; TaMax_C: 125°C
C2 = CMP-0011150-1: CAP, AL, 150 uF, 35 V, +/- 20%, 0.17 ohm, SMD; Manufacturer: Nichicon; TaMin_C: -55°C; ESR_ohm: 0.17; Polarized: Y; SizeAreaWB_mm2: 113.3; U/M: EA; Value: 150uF; TaMax_C: 105°C; SizeZ_mm: 10.2; SizeX_mm: 9; SizeY_mm: 8.3; Cap_Case: 8x10; SizeArea_mm2: 74.7; CompType: Capacitor; Cap_F: 150µF; IRMS_A: 450mA; AEC Category: Q200
C3 = CMP-0012293-3: CAP, Electric Double Layer, 47000 uF, 5.5 V, +80/-20%, TH; Manufacturer: Elna; TaMin_C: -25°C; Polarized: Y; Value1: Unknown; TaMax_C: 70°C; Tolerance_%: 80%; Value2: 5.5V; CompType: Capacitor; AEC Category: Q200
C4-C6 = CMP-0007068-4: CAP, CERM, 2.2 uF, 16 V, +/- 20%, X7S, AEC-Q200 Grade 1, 0603; Manufacturer: TDK; TaMin_C: -55°C; Polarized: N; SizeAreaWB_mm2: 4.68; Value1: Unknown; U/M: EA; Value: 2.2uF; TaMax_C: 125°C; SizeZ_mm: 1; SizeX_mm: 1.6; SizeY_mm: 0.8; Cap_Case: 0603; Value2: 16V; SizeArea_mm2: 1.28; AEC Qualified: Y; Cap_F: 2.2µF; AEC Category: Q200
C8 C10-C13 C15 C111 C115 C116 = CMP-0007068-4: CAP, CERM, 2.2 uF, 16 V, +/- 20%, X7S, AEC-Q200 Grade 1, 0603; Manufacturer: TDK; SizeAreaWB_mm2: 4.68; Cap_F: 2.2µF; Value1: Unknown; Value2: 16V; Value: 2.2uF; AEC Grade: 1; SizeX_mm: 1.6; TaMin_C: -55°C; AEC Category: Q200; U/M: EA; TaMax_C: 125°C; SizeArea_mm2: 1.28; Polarized: N; SizeY_mm: 0.8; Cap_Case: 0603; AEC Qualified: Y
C9 = CMP-0064967-2: CAP, CERM, 0.47 uF, 10 V,+/- 10%, X7S, 0402; Manufacturer: MuRata; TaMin_C: -55°C; Polarized: N; SizeAreaWB_mm2: 3; Value1: Unknown; U/M: EA; Value: 0.47uF; TaMax_C: 125°C; SizeZ_mm: 0.6; SizeX_mm: 1; SizeY_mm: 0.5; Cap_Case: 0402; Value2: 10V; Cap_F: 470nF; AEC Category: Q200
C14 = CMP-0064967-2: CAP, CERM, 0.47 uF, 10 V,+/- 10%, X7S, 0402; Manufacturer: MuRata; TaMin_C: -55°C; Polarized: N; SizeAreaWB_mm2: 3; Value1: Unknown; U/M: EA; Value: 0.47uF; TaMax_C: 125°C; SizeZ_mm: 0.6; SizeX_mm: 1; SizeY_mm: 0.5; Cap_Case: 0402; Value2: 10V; CompType: Capacitor; Cap_F: 470nF; AEC Category: Q200
C16 C17 = CMP-0087302-2: CAP CER 6PF 50V C0G 0402; Manufacturer: Murata; AEC Qualified: Yes; TempCo: 30ppm/°C; AEC Grade: Grade 1; SizeZ_mm: 0.9mm
C23 C34 C35 C37-C44 C93 C99 C100 C106 = CMP-0006351-2: CAP, CERM, 0.1 uF, 16 V, +/- 10%, X7R, 0402; Manufacturer: MuRata; TaMin_C: -55°C; Polarized: N; SizeAreaWB_mm2: 3; Value1: Unknown; U/M: EA; Value: 0.1uF; TaMax_C: 125°C; SizeZ_mm: 0.6; SizeX_mm: 1; SizeY_mm: 0.5; Cap_Case: 0402; Value2: 16V; Cap_F: 100nF; AEC Category: Q200
C24-C33 = CMP-0009173-2: CAP, CERM, 47 uF, 6.3 V, +/- 20%, X7R, 1210; Manufacturer: MuRata; PartNumber: GCM32ER70J476ME19L; TaMin_C: -55°C; Polarized: N; SizeAreaWB_mm2: 14.7; Value1: Unknown; U/M: EA; TaMax_C: 125°C; SizeZ_mm: 2.8; SizeX_mm: 3.2; SizeY_mm: 2.5; Cap_Case: 1210; Value2: 6.3V; SizeArea_mm2: 8; CompType: Capacitor; AEC Category: Q200
C36 C47 C58 C69 C78 C114 = CMP-0007965-2: CAP, CERM, 10 uF, 16 V, +/- 10%, X7S, AEC-Q200 Grade 1, 0805; Manufacturer: TDK; TaMin_C: -55°C; Polarized: N; SizeAreaWB_mm2: 6.75; Value1: Unknown; U/M: EA; Value: 10uF; TaMax_C: 125°C; SizeZ_mm: 1.45; SizeX_mm: 2; SizeY_mm: 1.25; Cap_Case: 0805; Value2: 16V; SizeArea_mm2: 2.5; AEC Qualified: Y; Cap_F: 10µF; AEC Grade: 1; AEC Category: Q200
C45 C49 = CMP-0086484-2: Chip Multilayer Ceramic Capacitors for Automotive; Manufacturer: Murata; TempCo: +22/-33%; Tolerance_%: 20%; SizeZ_mm: 1.9mm; AEC Qualified: Yes; VDC_V: 4V; AEC Grade: Grade 1
C46 C48 C50-C53 C56 C57 = CMP-0086484-2: Chip Multilayer Ceramic Capacitors for Automotive; Manufacturer: Murata; SizeZ_mm: 1.9mm; AEC Qualified: Yes; VDC_V: 4V; TempCo: +22/-33%; AEC Grade: Grade 1; Tolerance_%: 20%
C54 C55 C59-C66 = CMP-0082680-1: CAP, CERM, 10 µF, 4 V,+/- 20%, 1.6x0.8mm; PartNumber: NFM18HC106D0G3; Manufacturer: MuRata; Cap_F: 10µF; IRMS_A: 2A; SizeAreaWB_mm2: 4.68; SizeArea_mm2: 1.28; AEC Qualified: N; AEC Category: Q200; SizeZ_mm: 1.35; TempCo: Unknown; SizeY_mm: 0.8; VDC_V: 4V; U/M: EA; CompType: Capacitor; SizeX_mm: 1.6; Cap_Case: 0603
C67 C68 C70-C77 = CMP-0086486-3: 3 Terminals Chip Multilayer Ceramic Capacitor (EMIFIL); Manufacturer: Murata; Tolerance_%: 20%; SizeZ_mm: 0.5mm; AEC Qualified: No; VDC_V: 4V
C79 = CMP-0750066-1: CAP, TA, 680 µF, 6.3 V, +/- 10%, 0.023 ohm, AEC-Q200 Grade 1, SMD; Manufacturer: Kemet; AEC Category: Q200; AEC Grade: 1; VDC_V: 6.3V; TaMin_C: -55°C; Cap_Case: 7343; SizeX_mm: 7.3; SizeY_mm: 4.3; SizeAreaWB_mm2: 58.59; AEC Qualified: Y; SizeZ_mm: 4; Value: 680uF; CompType: Capacitor; SizeArea_mm2: 31.39; TaMax_C: 125°C; ESR_ohm: 0.023
C101-C105 = CMP-0006922-4: CAP, CERM, 3300 pF, 50 V, +/- 10%, X7R, 0603; Manufacturer: Kemet; TaMin_C: -55°C; Polarized: N; SizeAreaWB_mm2: 4.68; Value1: Unknown; U/M: EA; Value: 3300pF; TaMax_C: 125°C; SizeZ_mm: 1; SizeX_mm: 1.6; SizeY_mm: 0.8; Cap_Case: 0603; Value2: 50V; SizeArea_mm2: 1.28; Cap_F: 3.3nF; AEC Category: Q200
C112 C113 = CMP-0007306-5: CAP, CERM, 22 uF, 6.3 V, +/- 20%, X5R, 0603; Manufacturer: MuRata; TaMin_C: -55°C; Polarized: N; SizeAreaWB_mm2: 4.68; Value1: Unknown; U/M: EA; Value: 22uF; TaMax_C: 85°C; SizeZ_mm: 1; SizeX_mm: 1.6; SizeY_mm: 0.8; Cap_Case: 0603; Value2: 6.3V; SizeArea_mm2: 1.28; Cap_F: 22µF; AEC Category: Q200
C117 = CMP-0011130-1: CAP, AL, 470 uF, 16 V, +/- 20%, 0.17 ohm, SMD; Manufacturer: Nichicon; TaMin_C: -55°C; ESR_ohm: 0.17; Polarized: Y; SizeAreaWB_mm2: 113.3; U/M: EA; Value: 470uF; TaMax_C: 105°C; SizeZ_mm: 10.2; SizeX_mm: 9; SizeY_mm: 8.3; Cap_Case: 8x10; SizeArea_mm2: 74.7; CompType: Capacitor; Cap_F: 470µF; IRMS_A: 450mA; AEC Category: Q200
D1 = CMP-0085753-1: Diode, Zener, 10 V, 300 mW, SOD-323; Manufacturer: ON Semiconductor; SizeAreaWB_mm2: 8.695; SizeY_mm: 1.35; SizeX_mm: 2.7; RJA_CperW: 416; Value1: 0.3W; SizeArea_mm2: 3.645; AEC Category: Q101; Power_W: 300mW; AEC Qualified: N; SizeZ_mm: 1
D3-D5 = CMP-0002849-2: LED, Blue, SMD; Manufacturer: OSRAM; Tjmax_C: 95°C; Value1: W; Io_A: 150mA; Vf_V: 2.85V
J1-J6 = CMP-0055529-1: Terminal Block, 5mm, 2x1, R/A, TH; Manufacturer: Phoenix Contact; Cert_VDE: Y; Pitch_mm: 5; Gender: Female; Row_Count: 1; Voltage_V: 400V; Current_A: 16A; CNHeader: FALSE; CT: TRUE
J7-J11 J15 = CMP-0075454-1: Header, 100mil, 11x1, Gold, TH; Manufacturer: Samtec; Pitch_mm: 2.54; Cert_VDE: N; Gender: Male; Cert_CSA: Y; Voltage_V: 550V; Green_REACh: Passed; Current_A: 6.3A; CT: False; Green_Lifecycle: Active; Row_Count: 1; CNHeader: True
J12-J14 = CMP-0075416-1: Header, 100mil, 7x1, Gold, TH; Manufacturer: Samtec; Pitch_mm: 2.54; Cert_VDE: N; Gender: Male; Cert_CSA: Y; Voltage_V: 550V; Green_REACh: Passed; Current_A: 6.3A; CT: False; Green_Lifecycle: Active; Row_Count: 1; CNHeader: True
J16-J18 J21 = CMP-0084558-1: Header, 2.54mm, 2x1, Tin, TH; Manufacturer: Samtec; Cert_UL: Y; Row_Count: 1; Pitch_mm: 2.54; Gender: Male; Current_A: 6.3A; Voltage_V: 550V; Shrouded: N
J19 J20 J26 J37 J47 = CMP-0054796-4: Header, 2.54 mm, 3x1, Gold, TH; Manufacturer: Wurth Elektronik; Green_Lifecycle: Active; Green_REACh: Passed; CT: FALSE; CNHeader: TRUE
J23-J25 = CMP-0075020-1: JUMPER TIN SMD; Manufacturer: Harwin; CNHeader: False; Green_Lifecycle: Active; Green_REACh: Passed; CompType: Jumper SMT
J32-J36 = CMP-0075495-1: SMA Jack, Straight, 50 Ohm, Gold, TH; Manufacturer: Samtec; Green_REACh: Incomplete; CT: True; Green_Lifecycle: Not Set; CNHeader: False
J39-J41 = CMP-0075402-1: Header, 100mil, 3x1, Gold, SMT; Manufacturer: Samtec; Green_REACh: Passed; CT: False; Green_Lifecycle: Active; CNHeader: True
J42-J44 = CMP-0075491-1: Header, 100mil, 2x1, Tin, SMD; Manufacturer: Samtec; Pitch_mm: 2.54; Gender: Male; Cert_CSA: Y; Current_A: 5.4A; Voltage_V: 475V; CT: False; Shrouded: N; Row_Count: 1; CNHeader: True
L1-L5 = CMP-0085838-1: Inductor, Thin Film, 470 nH, 5.3 A, 0.021 ohm, AEC-Q200 Grade 0, SMD; Manufacturer: TDK; PartNumber: TFM322512ALMAR47MTAA; Value2: 5.3A; DCR_ohm: 0.021; SizeArea_mm2: 8; SizeAreaWB_mm2: 14.7; Isat: 6.9A @ 30% inductance drop; AEC Qualified: Y; SizeY_mm: 2.5; AEC Category: Q200; SizeX_mm: 3.2; Irms: 5.3A @ 40C rise; SizeZ_mm: 1.2; AEC Grade: 0
NT1 NT2 = CMP-0078142-4: Single point connection between nets.
Q1 = CMP-0100008-1: MOSFET, N-CH, 30 V, 27.2 A, AEC-Q101, SO-8FL; Manufacturer: ON Semiconductor; Alternate Manufacturer: None; Vgs_V: 20V; SizeAreaWB_mm2: 58.2725; SizeArea_mm2: 31.6725; Value1: ? ohm; QgTyp_nC: 30; VdsMax_V: 30V; IdsMax_A: 27.2A; Value: 30V; AEC Qualified: Y; AEC Category: Q101; SizeX_mm: 6.15; SizeY_mm: 5.15; ChType: N; SizeZ_mm: 1.1; Value2: 30 nC; ChMode: Enhancement
R1-R7 R26 R35 R40 R58 R65 R67 R83 = CMP-0027007-2: RES, 0, 5%, 0.063 W, AEC-Q200 Grade 0, 0402; Manufacturer: KOA Speer; Power_W: 63mW; TempCo: ppm/C; Value_Code: 0000; U/M: EA; Value: 0; EIA_Code: E24; SizeX_mm: 1; SizeY_mm: 0.5; SizeZ_mm: 0.6; Value2: 0.063W; AEC Qualified: Y; AEC Category: Q200
R8-R18 R28 R33 R37 R38 = CMP-0026825-5: RES, 10 k, 5%, 0.063 W, AEC-Q200 Grade 0, 0402; Manufacturer: Vishay-Dale; Power_W: 63mW; TempCo: 200 ppm/C; Value_Code: 10k0; Value: 10k; EIA_Code: E24; SizeX_mm: 1; SizeY_mm: 0.5; SizeZ_mm: 0.6; Value2: 0.063W; AEC Qualified: Y; VDC_V: 50V; AEC Category: Q200; AEC Grade: 0
R20 R21 R30 = CMP-0026882-3: RES, 240, 5%, 0.063 W, AEC-Q200 Grade 0, 0402; Manufacturer: Vishay-Dale; Power_W: 63mW; TempCo: 200 ppm/C; Value_Code: 240R; Value: 240; EIA_Code: E24; SizeX_mm: 1; SizeY_mm: 0.5; SizeZ_mm: 0.6; Value2: 0.063W; AEC Qualified: Y; VDC_V: 50V; AEC Category: Q200; AEC Grade: 0
R22-R24 = CMP-0026854-5: RES, 1.2 k, 5%, 0.063 W, AEC-Q200 Grade 0, 0402; Manufacturer: Vishay-Dale; Power_W: 63mW; TempCo: 200 ppm/C; Value_Code: 1k20; Value: 1.2k; EIA_Code: E24; SizeX_mm: 1; SizeY_mm: 0.5; SizeZ_mm: 0.6; Value2: 0.063W; AEC Qualified: Y; VDC_V: 50V; AEC Category: Q200; AEC Grade: 0
R25 = CMP-0015357-3: RES, 0.002, 2%, 1 W, 0508; PartNumber: KRL2012E-M-R002-G-T5; Manufacturer: Susumu Co Ltd; Value: 0.002; Res_ohm: 2m; Value_Code: 2L000; Power_W: 1W; TempCo: 100 ppm/C; U/M: EA; SizeArea_mm2: 2.5; SizeAreaWB_mm2: 6.75; SizeX_mm: 1.25; SizeY_mm: 2; SizeZ_mm: 1; AEC Category: Q200
R32 R51 R54 = CMP-0026824-3: RES, 100, 5%, 0.063 W, AEC-Q200 Grade 0, 0402; Manufacturer: Vishay-Dale; Power_W: 63mW; TempCo: 200 ppm/C; Value_Code: 100R; Value: 100; EIA_Code: E24; SizeX_mm: 1; SizeY_mm: 0.5; SizeZ_mm: 0.6; Value2: 0.063W; AEC Qualified: Y; VDC_V: 50V; AEC Category: Q200; AEC Grade: 0
S1 = CMP-0002183-2: Switch, Slide, SPDT, 0.2A, J Lead, SMD; Manufacturer: Copal Electronics; CurrentRating_mA: 200A; SwitchFunction: On-On; VDC_V: 12V; PositionCount: 2
TP1 TP2 = CMP-0055137-2: Test Point, Miniature, Red, TH; Manufacturer: Keystone Electronics; CNHeader: FALSE; Green_Lifecycle: Active; Green_REACh: Passed; ContactFinish: Silver; CT: TRUE
TP3-TP5 TP14 = CMP-0075188-1: Test Lead clips and hooks, SMT; Manufacturer: Harwin; CNHeader: False; Current_A: 2A; CompType: Test Point; ContactFinish: Tin; CT: True
TP6-TP13 = CMP-0055141-2: Test Point, Miniature, Yellow, TH; Manufacturer: Keystone Electronics; CNHeader: FALSE; Green_Lifecycle: Active; Green_REACh: Passed; ContactFinish: Silver; CT: TRUE
U1 = CMP-0085385-6: Power Management IC (PMIC) With 4-Phase 14-A Buck for Processors, RVJ0056A (VQFN-56); Manufacturer: Texas Instruments; SizeArea_mm2: 64; SizeAreaWB_mm2: 100; AEC Qualified: Y; SizeX_mm: 8; AEC Category: Q200; SizeZ_mm: 1
U2 = CMP-0065405-2: AEC-Q100 Quad Comparator, PW0014A (TSSOP-14); Manufacturer: Texas Instruments; CompType: IC; SizeY_mm: 5.0; SizeAreaWB_mm2: 58.8; Rating: Automotive; SizeZ_mm: 1.2; AEC Category: Q200; AEC Qualified: Y; SizeArea_mm2: 32.0; SizeX_mm: 6.4
U13 = CMP-0073729-1: Automotive Catalog, Dual, 200mA, Low-IQ Low-Dropout Regulator for Portable Devices, DSE0006A (WSON-6); Alternate Manufacturer: Texas Instruments; SizeAreaWB_mm2: 6.25; U/M: EA; SizeZ_mm: 0.8; SizeX_mm: 1.5; SizeArea_mm2: 2.25; CompType: IC
U14 = CMP-0037269-2: 5 V, Boost Charge Pump, 300 mA, 2.7 to 5.4 V Input with Synchonrization pin, -40 to 85 degC, 20-pin SOP (PWP20), Green (RoHS & no Sb/Br); Manufacturer: Texas Instruments; Vin(Min)(V): 2.7; Synchronization Pin: TRUE; Vin(Max)(V): 5.4; Efficiency(Typ)(%): 70; Switching Frequency(Max)(kHz): 400; Vout(Min)(V): 4.8; Preset Vout(V): 5; Vout(Max)(V): 5.25; Iq(Typ)(mA): 0.06; Iout(Max)(A): 0.3
Y1 = CMP-0860001-1: Crystal, 32.768 KHz, 9 pF, AEC-Q200 Grade 1, SMD; Manufacturer: NDK; AEC Category: Q200; Load Capacitance: 9 pF; SizeAreaWB_mm2: 10.5; AEC Grade: 1; SizeY_mm: 1.5; TaMax_C: 125°C; SizeArea_mm2: 4.8; AEC Qualified: Y; SizeZ_mm: 0.9; TaMin_C: -40°C; SizeX_mm: 3.2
